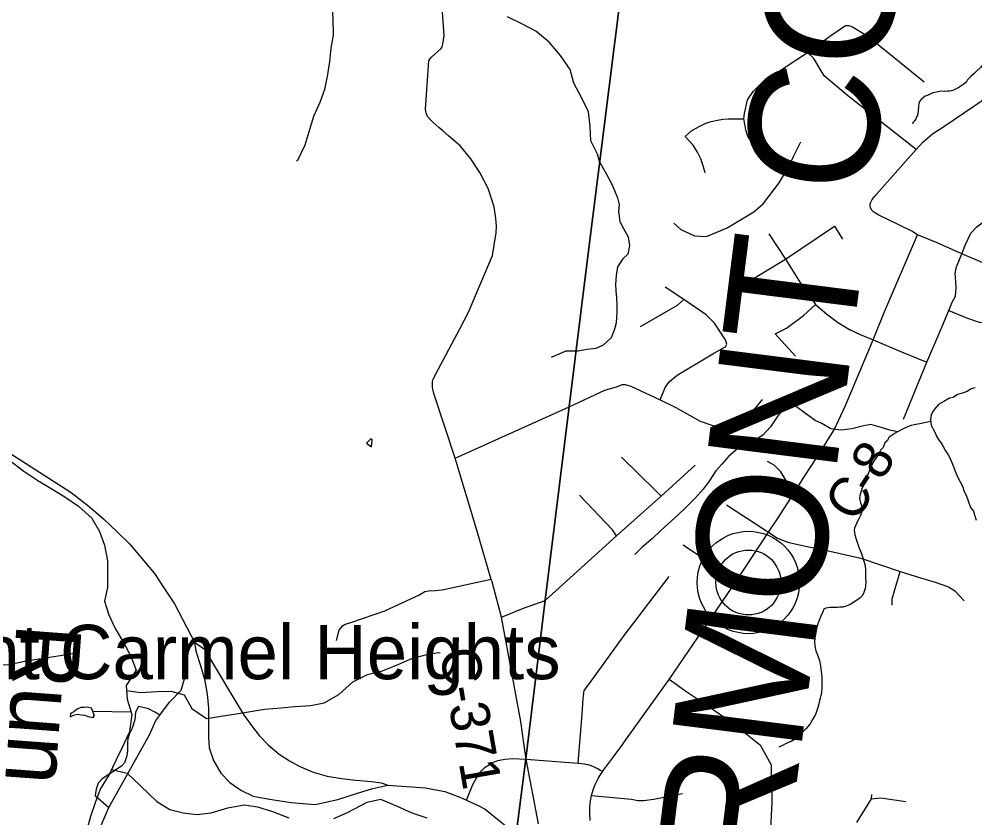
# Model space of a CAD drawing. Extents: x 0 to 34, y 0 to 22.
# Drawn here: x 5.518 to 6.213, y 17.164 to 17.744 of the extents above; entities that cross this region are included whole.
import ezdxf

# ---------------------------------------------------------------- set-up
doc = ezdxf.new("R2010")
doc.units = 0
for name, color, linetype in [('GM_X_Corporation', 7, 'Continuous'), ('GM_X_County_Road', 7, 'Continuous'), ('GM_X_County_Road_Text', 7, 'Continuous'), ('GM_X_County_Text', 7, 'Continuous'), ('GM_X_Minor_Lake', 7, 'Continuous'), ('GM_X_Minor_River', 7, 'Continuous'), ('GM_X_Minor_River_Text', 7, 'Continuous'), ('GM_X_State_Route', 7, 'Continuous'), ('GM_X_Township', 7, 'Continuous'), ('GM_X_Township_Road', 7, 'Continuous'), ('GM_X_Unincorporated', 7, 'Continuous'), ('GM_X_Unincorporated_Location', 7, 'Continuous'), ('GM_X_Unincorporated_Text', 7, 'Continuous'), ('SH_Cut_Line', 7, 'Continuous')]:
    doc.layers.add(name, color=color, linetype=linetype)

msp = doc.modelspace()

# ---------------------------------------------------------------- linework, layer by layer
at = {"layer": 'GM_X_Corporation'}
msp.add_lwpolyline([(5.72112, 15.95514), (5.75974, 16.24674), (5.8051, 16.58756), (5.8147, 16.66168), (5.82679, 16.74115), (5.83718, 16.83132), (5.84257, 16.87203), (5.86313, 17.02725), (5.87205, 17.09459), (5.87488, 17.11595), (5.87933, 17.15186), (5.88642, 17.2068), (5.90033, 17.32196), (5.91784, 17.46266), (5.93092, 17.56818), (6.04699, 18.48945)], dxfattribs=at)
at = {"layer": 'GM_X_County_Road'}
for p, q in [((5.88654, 17.20654), (5.88515, 17.21642)), ((5.89561, 17.15957), (5.88654, 17.20654))]:
    msp.add_line(p, q, dxfattribs=at)
for points in [[(5.82314, 17.66553), (5.81884, 17.66925), (5.81495, 17.67334), (5.81393, 17.67579), (5.81338, 17.6787), (5.8158, 17.71381), (5.8166, 17.71522), (5.81777, 17.71661), (5.82476, 17.7229), (5.82548, 17.72411), (5.82598, 17.72592), (5.82709, 17.73197), (5.8223, 17.79711), (5.82121, 17.8013), (5.81983, 17.80439), (5.81822, 17.80608), (5.81408, 17.80948), (5.80605, 17.81443), (5.80411, 17.81619), (5.80235, 17.81852), (5.80081, 17.82483), (5.80016, 17.83206), (5.80011, 17.83254)], [(5.9608, 17.22281), (5.9906, 17.26439), (6.03947, 17.33601), (6.06277, 17.37129), (6.06932, 17.38118), (6.08108, 17.39948), (6.08874, 17.41158), (6.09893, 17.42717), (6.10527, 17.43729), (6.1105, 17.44574), (6.11861, 17.46341), (6.13876, 17.51105), (6.14688, 17.531), (6.17101, 17.58747), (6.16691, 17.59017), (6.14951, 17.59863), (6.14305, 17.60179), (6.13924, 17.60403), (6.13779, 17.6053), (6.13686, 17.60699), (6.13654, 17.60891), (6.1368, 17.61066), (6.13803, 17.61317), (6.13982, 17.61524), (6.14702, 17.62343), (6.17003, 17.64951), (6.17501, 17.6548), (6.17862, 17.65802), (6.18205, 17.66074), (6.1901, 17.66627), (6.21206, 17.68092), (6.22902, 17.69252)], [(5.88515, 17.21642), (5.88271, 17.23372), (5.86859, 17.30966), (5.86177, 17.33527), (5.86124, 17.33705), (5.85066, 17.37276), (5.83566, 17.42269), (5.83488, 17.42508), (5.81952, 17.47207), (5.81879, 17.4754), (5.8186, 17.47685), (5.81842, 17.47937), (5.81857, 17.48075), (5.81885, 17.48203), (5.81924, 17.48316), (5.82257, 17.48967), (5.83842, 17.51913), (5.84458, 17.53134), (5.86209, 17.57255), (5.86486, 17.58883), (5.8651, 17.59376), (5.86465, 17.59935), (5.86338, 17.60787), (5.85897, 17.6211), (5.85282, 17.63285), (5.84643, 17.6427), (5.83889, 17.65183), (5.83016, 17.65946), (5.82601, 17.66305), (5.82314, 17.66553)], [(6.21966, 17.56668), (6.20325, 17.57373), (6.18546, 17.58168), (6.17101, 17.58747)], [(5.57488, 17.15228), (5.5831, 17.17132), (5.61287, 17.22408), (5.61728, 17.23443), (5.62017, 17.23831), (5.62727, 17.24787), (5.63569, 17.25657), (5.63826, 17.26477), (5.63954, 17.27328), (5.64119, 17.28467), (5.64269, 17.28799), (5.64551, 17.29149)], [(5.93313, 17.16177), (5.93297, 17.16699), (5.93298, 17.17159), (5.9332, 17.17388), (5.93341, 17.17617), (5.93414, 17.18012), (5.93531, 17.18425), (5.93676, 17.18805), (5.93886, 17.19235), (5.94029, 17.19476), (5.94129, 17.19626), (5.94207, 17.19739), (5.94651, 17.2033), (5.94928, 17.20713), (5.95696, 17.21746), (5.9608, 17.22281)], [(5.84314, 17.17668), (5.84791, 17.18795), (5.85007, 17.19198), (5.85224, 17.19531), (5.85383, 17.19761), (5.85686, 17.20064), (5.85988, 17.20267), (5.86234, 17.20411), (5.86595, 17.20555), (5.87114, 17.20656), (5.87677, 17.20685), (5.88654, 17.20654)], [(5.88654, 17.20654), (5.92445, 17.20364), (5.925, 17.2036), (5.92704, 17.20339), (5.92906, 17.20305), (5.93105, 17.2026), (5.93145, 17.20248), (5.93301, 17.20202), (5.93366, 17.20178), (5.93397, 17.20167), (5.93493, 17.20132), (5.93601, 17.20085), (5.9368, 17.2005), (5.93862, 17.19957), (5.94038, 17.19853), (5.94207, 17.19739)]]:
    msp.add_lwpolyline(points, dxfattribs=at)
at = {"layer": 'GM_X_Minor_Lake'}
for p, q in [((5.77466, 17.43847), (5.7737, 17.43923)), ((5.57171, 17.23679), (5.57266, 17.23831))]:
    msp.add_line(p, q, dxfattribs=at)
for points in [[(5.7737, 17.43923), (5.77047, 17.43599), (5.77408, 17.43352), (5.77466, 17.43847)], [(5.57266, 17.23831), (5.57152, 17.24097), (5.57057, 17.24345), (5.56771, 17.24421), (5.56524, 17.24402), (5.56277, 17.24402), (5.56029, 17.24287), (5.55782, 17.24078), (5.55535, 17.23964), (5.55516, 17.23717), (5.55763, 17.23831), (5.56048, 17.23926), (5.56315, 17.23869), (5.56562, 17.2385), (5.56809, 17.23736), (5.57056, 17.23698), (5.57171, 17.23679)]]:
    msp.add_lwpolyline(points, dxfattribs=at)
at = {"layer": 'GM_X_Minor_River'}
msp.add_line((5.57266, 17.23831), (5.57171, 17.23679), dxfattribs=at)
for points in [[(5.73021, 17.81507), (5.73745, 17.80537), (5.74031, 17.79528), (5.74088, 17.78501), (5.7424, 17.77493), (5.74392, 17.76408), (5.74526, 17.75438), (5.74602, 17.74486), (5.7464, 17.7325), (5.74468, 17.72299), (5.74373, 17.71347), (5.74221, 17.70396), (5.73992, 17.69311), (5.73668, 17.6836), (5.73211, 17.67352), (5.72867, 17.66229), (5.72563, 17.65259), (5.72048, 17.64155), (5.71953, 17.64098)], [(5.94015, 17.63994), (5.93848, 17.64613), (5.93371, 17.65583), (5.93314, 17.66649), (5.932, 17.67676), (5.92705, 17.68666), (5.92133, 17.69769), (5.91847, 17.70758), (5.91161, 17.71767), (5.90342, 17.72756), (5.89351, 17.73555), (5.88341, 17.74069), (5.87312, 17.74582)], [(6.23526, 17.7315), (6.23142, 17.72576), (6.22909, 17.72374), (6.22849, 17.72261), (6.22634, 17.7202), (6.22497, 17.71853), (6.22302, 17.71669), (6.22165, 17.71502), (6.22048, 17.71372), (6.21969, 17.7126), (6.21871, 17.71149), (6.21675, 17.70907), (6.21402, 17.7063), (6.21207, 17.70445), (6.21013, 17.7028), (6.20838, 17.70113), (6.2074, 17.70002), (6.20661, 17.69872), (6.20486, 17.69686)], [(6.20486, 17.69686), (6.20254, 17.69541), (6.20061, 17.69432), (6.19869, 17.69323), (6.19676, 17.69233), (6.19543, 17.69199), (6.19428, 17.69183), (6.19276, 17.69187), (6.19086, 17.69173), (6.18839, 17.69179), (6.18496, 17.69112), (6.18362, 17.69078), (6.1821, 17.69063), (6.17883, 17.68901), (6.17672, 17.68811), (6.17536, 17.6872), (6.17381, 17.68591), (6.17263, 17.68443), (6.17202, 17.68274), (6.1718, 17.6816), (6.17176, 17.6799), (6.17153, 17.67839), (6.1715, 17.67725), (6.17105, 17.67422), (6.17045, 17.6731), (6.16984, 17.6716), (6.16886, 17.6703), (6.16769, 17.66919), (6.16766, 17.66805)], [(5.94015, 17.63994), (5.94489, 17.63145), (5.94855, 17.62473), (5.95073, 17.61974), (5.95289, 17.61438), (5.95431, 17.6094), (5.95383, 17.60447), (5.95463, 17.59704), (5.95737, 17.59204), (5.96067, 17.58608), (5.96167, 17.5796), (5.9604, 17.57335)], [(5.9604, 17.57335), (5.95679, 17.57005), (5.95307, 17.56424), (5.95199, 17.55779), (5.95149, 17.55172), (5.95177, 17.54678), (5.95224, 17.54163), (5.95251, 17.53631), (5.9526, 17.53117), (5.95206, 17.52339), (5.95063, 17.5181), (5.94843, 17.51263), (5.94263, 17.50724), (5.93726, 17.50487), (5.9306, 17.50406), (5.92435, 17.50297)], [(5.92435, 17.50297), (5.9154, 17.50297), (5.90532, 17.49859), (5.90475, 17.4984)], [(6.21309, 17.47634), (6.21003, 17.47547), (6.20714, 17.47364), (6.20351, 17.47241), (6.20007, 17.47136), (6.19699, 17.46935), (6.19432, 17.46866), (6.19009, 17.4663), (6.18624, 17.46411), (6.18331, 17.46077), (6.18173, 17.45834), (6.18072, 17.45552), (6.18045, 17.45267), (6.18093, 17.44924), (6.18237, 17.44635), (6.18382, 17.44365), (6.18489, 17.44115), (6.18634, 17.43864), (6.18817, 17.43612), (6.18999, 17.43322), (6.19144, 17.43052), (6.19308, 17.42801), (6.19453, 17.4255), (6.19596, 17.42204), (6.19738, 17.41839), (6.19845, 17.4157), (6.20024, 17.41166), (6.20204, 17.408), (6.20385, 17.40472), (6.20507, 17.40089), (6.20633, 17.3982), (6.20793, 17.39416), (6.2097, 17.38936), (6.21172, 17.38665), (6.21241, 17.38397), (6.21363, 17.38014)], [(6.15653, 17.44424), (6.15103, 17.44546), (6.14404, 17.44769), (6.13725, 17.44954), (6.13077, 17.44853), (6.12332, 17.4464), (6.11552, 17.44542), (6.10813, 17.44652), (6.10156, 17.45045), (6.09667, 17.45264), (6.08974, 17.45753), (6.08319, 17.46241), (6.07845, 17.4627), (6.0727, 17.45996), (6.069, 17.45509), (6.06411, 17.44797), (6.05867, 17.442), (6.05386, 17.43867), (6.04715, 17.43538), (6.04044, 17.43229), (6.03387, 17.42653), (6.02882, 17.42074), (6.02454, 17.41588), (6.01965, 17.40857), (6.01516, 17.40258), (6.00972, 17.39641), (6.00314, 17.38989), (5.99694, 17.38375), (5.99017, 17.3778), (5.98418, 17.37241), (5.97837, 17.36682), (5.97103, 17.36051), (5.9656, 17.3551)], [(6.18057, 17.45186), (6.17279, 17.45004), (6.16993, 17.44971), (6.1686, 17.44935), (6.1665, 17.44882), (6.16497, 17.44846), (6.16229, 17.44718), (6.16056, 17.44645), (6.15653, 17.44424), (6.15481, 17.44332), (6.15327, 17.44239), (6.15192, 17.44147), (6.15057, 17.44035), (6.14901, 17.43771), (6.14727, 17.43622), (6.14608, 17.43301), (6.14453, 17.43113), (6.14355, 17.42944), (6.14277, 17.42812), (6.1414, 17.42586), (6.14004, 17.42418), (6.13906, 17.42286), (6.13828, 17.42116), (6.13729, 17.41928), (6.13669, 17.41739), (6.1353, 17.4138), (6.13353, 17.41022), (6.13274, 17.40833), (6.13194, 17.40625), (6.13055, 17.40285), (6.12954, 17.39945), (6.12914, 17.39774), (6.12892, 17.39641), (6.12908, 17.3947), (6.12962, 17.39279), (6.13035, 17.39087), (6.13089, 17.38934), (6.13087, 17.38801), (6.13065, 17.3863), (6.13006, 17.3846), (6.12927, 17.3829), (6.12847, 17.38102), (6.12749, 17.37932), (6.12671, 17.37781), (6.12592, 17.37593), (6.12532, 17.37422), (6.1251, 17.3729), (6.12543, 17.36947), (6.12651, 17.36622), (6.12778, 17.36258), (6.12868, 17.35971), (6.12942, 17.35818), (6.13015, 17.35645), (6.13105, 17.35339), (6.13214, 17.35033), (6.13303, 17.34708), (6.13336, 17.34403), (6.13326, 17.33776), (6.13341, 17.33547), (6.13335, 17.33224), (6.13313, 17.33053), (6.13233, 17.32827), (6.13174, 17.32675), (6.13076, 17.32525), (6.12941, 17.32375), (6.12748, 17.32227), (6.1221, 17.31894), (6.11923, 17.31766), (6.11675, 17.31694), (6.11446, 17.31679), (6.11294, 17.31662), (6.11009, 17.31667), (6.10762, 17.31672), (6.10438, 17.3162), (6.10303, 17.31547), (6.10224, 17.31358), (6.10086, 17.31037), (6.09967, 17.30735), (6.09847, 17.30414), (6.09767, 17.30149), (6.09704, 17.29826), (6.09641, 17.29447), (6.09617, 17.29162), (6.09632, 17.28934), (6.09667, 17.28743), (6.0972, 17.28514), (6.09848, 17.28226), (6.09974, 17.27806), (6.10063, 17.27424), (6.10113, 17.27023), (6.10164, 17.26661), (6.1015, 17.25863), (6.10124, 17.25445), (6.10084, 17.25274), (6.10023, 17.25085), (6.09982, 17.24915), (6.0994, 17.24668), (6.0986, 17.24403), (6.09819, 17.24252), (6.0976, 17.24101), (6.0968, 17.23893)], [(5.51009, 17.42437), (5.52131, 17.41581), (5.53158, 17.40896), (5.54129, 17.40306), (5.55117, 17.39717), (5.56106, 17.39032), (5.57095, 17.38157), (5.57647, 17.37186), (5.58008, 17.36197), (5.58217, 17.35056), (5.58236, 17.34085), (5.58217, 17.33115), (5.58008, 17.32126), (5.58331, 17.31137), (5.58788, 17.30147), (5.59377, 17.2912), (5.5991, 17.28131), (5.60309, 17.27103), (5.59586, 17.26), (5.59643, 17.24992), (5.60004, 17.23888), (5.59814, 17.22633), (5.59282, 17.21491), (5.58825, 17.2054), (5.5835, 17.19531), (5.57703, 17.18466), (5.57322, 17.17477), (5.5698, 17.16487), (5.56733, 17.15498)], [(5.59607, 17.25637), (5.60613, 17.25486), (5.61831, 17.25563), (5.62839, 17.25582), (5.63789, 17.25315), (5.6436, 17.24326), (5.65425, 17.23603), (5.6649, 17.23775), (5.67574, 17.23927), (5.6862, 17.24098), (5.69647, 17.24269), (5.70846, 17.24365), (5.71835, 17.2446), (5.72995, 17.24555), (5.73965, 17.24726), (5.7503, 17.25335), (5.76057, 17.26268), (5.77122, 17.268), (5.78225, 17.27067), (5.79233, 17.27466), (5.80356, 17.27961), (5.81345, 17.28227), (5.82296, 17.28399), (5.8241, 17.2838)], [(5.59951, 17.24053), (5.5715, 17.24101)], [(6.0968, 17.23893), (6.09484, 17.23516), (6.09307, 17.23215), (6.08997, 17.2284), (6.08707, 17.2256), (6.08417, 17.22241), (6.08243, 17.22111), (6.08051, 17.22001), (6.07917, 17.21927), (6.07783, 17.21891), (6.07515, 17.21763), (6.07342, 17.21671), (6.0717, 17.21579), (6.07036, 17.21524)], [(5.5852, 17.19893), (5.59643, 17.19627), (5.60613, 17.18713), (5.61811, 17.17572), (5.62762, 17.16982), (5.63732, 17.16754), (5.64721, 17.16621), (5.65767, 17.16754), (5.66965, 17.17116), (5.68164, 17.17325), (5.69134, 17.17173), (5.70218, 17.16831), (5.71397, 17.16374)], [(5.74668, 17.16336), (5.75676, 17.16774), (5.77103, 17.17516), (5.78073, 17.17744), (5.7929, 17.17231), (5.80336, 17.16755), (5.81439, 17.16375)]]:
    msp.add_lwpolyline(points, dxfattribs=at)
at = {"layer": 'GM_X_State_Route'}
for points in [[(5.27243, 17.53038), (5.33307, 17.50616), (5.37117, 17.49394), (5.39928, 17.48804), (5.43183, 17.47517), (5.44836, 17.46962), (5.47777, 17.45001), (5.55587, 17.40031), (5.56892, 17.39), (5.57934, 17.38101), (5.58932, 17.37158), (5.59831, 17.36281), (5.6061, 17.35382), (5.6163, 17.34142), (5.62323, 17.33103)], [(5.62323, 17.33103), (5.63099, 17.31938), (5.64551, 17.29149)], [(5.64551, 17.29149), (5.64645, 17.28502), (5.64983, 17.27441), (5.65271, 17.26466), (5.65468, 17.25369), (5.65556, 17.24338), (5.65562, 17.2225), (5.65612, 17.21466), (5.65918, 17.20544), (5.6647, 17.19635), (5.67113, 17.18954), (5.67914, 17.18395), (5.68815, 17.17961), (5.70011, 17.17731), (5.71587, 17.17495), (5.73314, 17.17348), (5.74974, 17.17707), (5.76395, 17.18177), (5.77522, 17.18517), (5.78612, 17.18749)], [(5.64551, 17.29149), (5.65267, 17.28633), (5.65849, 17.27651), (5.67688, 17.24565), (5.68171, 17.23808), (5.68753, 17.22994), (5.69252, 17.22352), (5.69926, 17.21661), (5.70708, 17.21012), (5.71449, 17.2053), (5.72164, 17.2013), (5.73187, 17.19706), (5.74202, 17.19415), (5.75242, 17.19232), (5.76274, 17.19115), (5.77414, 17.19015), (5.78129, 17.18916), (5.78612, 17.18749)], [(5.78612, 17.18749), (5.81347, 17.1857), (5.82756, 17.18289), (5.83846, 17.17878), (5.84314, 17.17668), (5.85209, 17.17265), (5.85686, 17.1702), (5.87945, 17.1516)]]:
    msp.add_lwpolyline(points, dxfattribs=at)
at = {"layer": 'GM_X_Township'}
msp.add_lwpolyline([(5.72112, 15.95514), (5.75974, 16.24674), (5.8051, 16.58756), (5.8147, 16.66168), (5.82679, 16.74115), (5.83718, 16.83132), (5.84257, 16.87203), (5.86313, 17.02725), (5.87205, 17.09459), (5.87488, 17.11595), (5.87933, 17.15186), (5.88642, 17.2068), (5.90033, 17.32196), (5.91784, 17.46266), (5.93092, 17.56818), (6.04699, 18.48945)], dxfattribs=at)
at = {"layer": 'GM_X_Township_Road'}
for p, q in [((5.83488, 17.42508), (5.91796, 17.4624)), ((6.03947, 17.33601), (6.00061, 17.36204))]:
    msp.add_line(p, q, dxfattribs=at)
for points in [[(6.07569, 17.70975), (6.09119, 17.71995), (6.10808, 17.73233), (6.11884, 17.73969), (6.12111, 17.73965), (6.12393, 17.73864), (6.13502, 17.73189), (6.1758, 17.69869)], [(6.17003, 17.64951), (6.12016, 17.68879), (6.10327, 17.70291), (6.09559, 17.71568), (6.09119, 17.71995)], [(6.09151, 17.62788), (6.077, 17.63631), (6.0657, 17.64203), (6.06235, 17.64405), (6.05979, 17.64514), (6.05676, 17.64763), (6.0538, 17.6505), (6.05162, 17.65315), (6.0496, 17.65595), (6.04781, 17.65921), (6.04641, 17.66287), (6.04478, 17.67181), (6.04533, 17.67554), (6.04758, 17.68557), (6.05155, 17.69172), (6.05755, 17.69767), (6.07415, 17.70873), (6.07569, 17.70975)], [(6.01671, 17.63239), (6.01523, 17.63752), (6.0136, 17.6428), (6.01119, 17.64763), (6.00808, 17.6526), (6.00225, 17.6589), (6.00707, 17.66318), (6.0129, 17.66652), (6.01717, 17.66854), (6.02099, 17.66971), (6.02565, 17.67088), (6.02954, 17.6715), (6.03335, 17.67181), (6.03825, 17.67173), (6.04478, 17.67181)], [(5.9939, 17.59605), (5.99906, 17.59137), (6.00889, 17.58669), (6.01778, 17.58622), (6.03276, 17.59254), (6.05216, 17.60424), (6.05897, 17.61009), (6.0704, 17.62534), (6.077, 17.63631), (6.08097, 17.64426), (6.08636, 17.65503)], [(6.16082, 17.45344), (6.1778, 17.49481), (6.18686, 17.51575), (6.19395, 17.53239), (6.19625, 17.53849), (6.19865, 17.543), (6.19918, 17.54886), (6.19882, 17.55351), (6.19854, 17.55926), (6.19937, 17.56419), (6.20325, 17.57373), (6.20584, 17.58034), (6.20995, 17.58865), (6.21415, 17.59321), (6.24846, 17.61867), (6.2784, 17.64185), (6.28825, 17.65007)], [(6.04271, 17.55006), (6.07501, 17.56983), (6.1107, 17.59371), (6.11644, 17.58435)], [(6.06307, 17.58821), (6.07501, 17.56983), (6.08718, 17.55029), (6.09291, 17.5428), (6.09689, 17.53683), (6.10485, 17.53004), (6.11281, 17.52396), (6.12158, 17.51869), (6.12943, 17.51495), (6.13876, 17.51105), (6.15936, 17.50232), (6.1778, 17.49481)], [(5.98412, 17.46751), (5.98773, 17.47643), (5.9909, 17.48085), (5.99634, 17.48538), (6.02343, 17.5017), (6.03154, 17.506), (6.03253, 17.50807), (6.03145, 17.51114), (6.02343, 17.52335), (6.01754, 17.52924), (6.0011, 17.54046), (5.98752, 17.5495)], [(6.0011, 17.54046), (5.99628, 17.53611), (5.96947, 17.5206)], [(6.0825, 17.49938), (6.06752, 17.51553), (6.07583, 17.51963), (6.08811, 17.52887), (6.09689, 17.53683)], [(6.19395, 17.53239), (6.20675, 17.52705), (6.21587, 17.52399), (6.22296, 17.52316), (6.23054, 17.52399), (6.24323, 17.52531), (6.25015, 17.52547), (6.2574, 17.52415), (6.26301, 17.52086), (6.26741, 17.5138), (6.26911, 17.50668), (6.26845, 17.50108), (6.26597, 17.49399), (6.25889, 17.48608)], [(5.91796, 17.4624), (5.94371, 17.47456), (5.95296, 17.47736), (5.9564, 17.47863), (5.95848, 17.47859), (5.96263, 17.47757), (5.98412, 17.46751), (5.9955, 17.46197), (6.013, 17.45207), (6.02217, 17.44895), (6.02651, 17.44859), (6.03068, 17.44878), (6.03759, 17.45025), (6.04281, 17.45252), (6.04915, 17.45637), (6.05833, 17.46782)], [(5.98467, 17.39744), (5.98116, 17.40118), (5.95601, 17.42579)], [(5.90044, 17.3217), (5.95237, 17.36866), (5.98467, 17.39744), (6.00949, 17.41999)], [(6.08108, 17.39948), (6.07176, 17.41523), (6.06679, 17.4202), (6.06201, 17.42281)], [(5.95237, 17.36866), (5.94931, 17.37307), (5.92528, 17.39823)], [(6.03218, 17.39119), (6.06277, 17.37129), (6.0688, 17.36719), (6.07662, 17.36403), (6.09091, 17.36095), (6.10729, 17.35765), (6.12993, 17.3526), (6.15841, 17.3427), (6.17325, 17.33831), (6.1838, 17.33512), (6.19359, 17.3316), (6.1982, 17.32885), (6.20502, 17.32149)], [(6.15258, 17.3183), (6.15258, 17.32303), (6.15841, 17.3427)], [(5.86124, 17.33705), (5.82558, 17.32926), (5.82044, 17.3288), (5.8155, 17.32854), (5.81283, 17.32803), (5.80937, 17.32583), (5.78367, 17.31387), (5.75958, 17.30568), (5.75499, 17.30427), (5.75268, 17.3028), (5.75035, 17.30019), (5.74847, 17.29264)], [(5.92445, 17.20364), (5.92731, 17.23924), (5.92794, 17.25049), (5.92882, 17.25644), (5.93262, 17.26149), (5.95718, 17.29529), (5.99048, 17.3392)], [(5.86859, 17.30966), (5.88454, 17.3162), (5.90044, 17.3217)], [(5.49446, 17.27943), (5.50089, 17.27614), (5.50427, 17.27533), (5.50732, 17.27509), (5.51053, 17.27517), (5.51535, 17.27614), (5.52207, 17.27765), (5.53075, 17.279), (5.55863, 17.28342)], [(6.01505, 17.24729), (6.00346, 17.25518), (5.9906, 17.26439)], [(6.06496, 17.19109), (6.06496, 17.20203), (6.0572, 17.21611), (6.03658, 17.23265), (6.01505, 17.24729)], [(5.62017, 17.23831), (5.6166, 17.24064), (5.61206, 17.24291), (5.60909, 17.24363), (5.60483, 17.24468), (5.60258, 17.2405), (5.60202, 17.23504), (5.60017, 17.22901), (5.59832, 17.22507), (5.59695, 17.22129), (5.59679, 17.21888), (5.59672, 17.2131), (5.59623, 17.20892), (5.59471, 17.20378), (5.59238, 17.20129), (5.57839, 17.19204), (5.57534, 17.18891), (5.57405, 17.18473), (5.57325, 17.17999), (5.5831, 17.17132)], [(6.06383, 17.07731), (6.06476, 17.09178), (6.06455, 17.1369), (6.06455, 17.15548), (6.06537, 17.17508), (6.06537, 17.18304), (6.06496, 17.19059), (6.06496, 17.19109)], [(5.93414, 17.18012), (5.9632, 17.17727), (5.96768, 17.17651), (5.97197, 17.1763), (5.97942, 17.17732), (6.00035, 17.18151)], [(6.12685, 17.16048), (6.13769, 17.1775), (6.13793, 17.18082)], [(6.13769, 17.1775), (6.14432, 17.17833), (6.16267, 17.17573)]]:
    msp.add_lwpolyline(points, dxfattribs=at)
at = {"layer": 'GM_X_Unincorporated'}
for radius in [0.0372, 0.02358]:
    msp.add_circle((6.04815, 17.33482), radius, dxfattribs=at)
at = {"layer": 'GM_X_Unincorporated_Location'}
msp.add_line((6.04815, 17.33482), (6.04815, 17.33482), dxfattribs=at)
at = {"layer": 'SH_Cut_Line'}
for points in [[(5.72112, 15.95514), (5.75974, 16.24674), (5.8051, 16.58756), (5.8147, 16.66168), (5.82679, 16.74115), (5.83718, 16.83132), (5.84257, 16.87203), (5.86313, 17.02725), (5.87205, 17.09459), (5.87488, 17.11595), (5.87933, 17.15186), (5.88642, 17.2068), (5.90033, 17.32196), (5.91784, 17.46266), (5.93092, 17.56818), (6.04699, 18.48945)], [(6.04699, 18.48945), (5.93092, 17.56818), (5.91784, 17.46266), (5.90033, 17.32196), (5.88642, 17.2068), (5.87933, 17.15186), (5.87488, 17.11595), (5.87205, 17.09459), (5.86313, 17.02725), (5.84257, 16.87203), (5.83718, 16.83132), (5.82679, 16.74115), (5.8147, 16.66168), (5.8051, 16.58756), (5.75974, 16.24674), (5.72112, 15.95514)]]:
    msp.add_lwpolyline(points, dxfattribs=at)

# ---------------------------------------------------------------- texts
at = {"layer": 'GM_X_County_Road_Text'}
for s, height, rotation, p in [('8', 0.02841, 59.45702, (6.14526, 17.40789)), ('C', 0.02841, 57.17378, (6.12567, 17.3774)), ('-', 0.02841, 57.40426, (6.13839, 17.39711)), ('C-371', 0.028409, 279.81889, (5.82349, 17.2851))]:
    msp.add_text(s, height=height, rotation=rotation, dxfattribs=at).set_placement(p)
at = {"layer": 'GM_X_County_Text'}
msp.add_text('CLERMONT COUNTY', height=0.094697, rotation=82.79761, dxfattribs=at).set_placement((6.04352, 16.87439))
at = {"layer": 'GM_X_Minor_River_Text'}
msp.add_text('Run', height=0.04736, rotation=265.75847, dxfattribs=at).set_placement((5.51629, 17.30567))
at = {"layer": 'GM_X_Unincorporated_Text'}
msp.add_text('Mount Carmel Heights', height=0.0394886, rotation=0.00001, dxfattribs=at).set_placement((5.38629, 17.26456))

doc.saveas('drawing.dxf')
